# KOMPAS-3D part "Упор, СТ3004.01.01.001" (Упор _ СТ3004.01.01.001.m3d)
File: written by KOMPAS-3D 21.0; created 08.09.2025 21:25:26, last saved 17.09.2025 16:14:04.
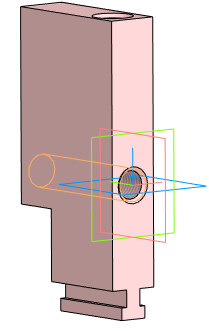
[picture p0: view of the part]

Document properties: Полное имя файла: C:\Users\Lutik\Yandex.Disk\Документы\Новая папка\Стапель №2\Стапель _ СТ3004.00.00.000\Опора _ СТ3004.01.00.000\3D\Кронштейн _ СТ3004.01.01.000\Упор _ СТ3004.01.01.001.m3d

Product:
- Part/product: Упор  | designation СТ3004.01.01.001
    Материал: Сталь 45  ГОСТ 1050-2013 (density 7810 kg/m3)
    Масса: 1.534235
    Форматы листов документа: A3

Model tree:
1. Эскиз:1
2. Элемент выдавливания:1
     Расстояние 1 = 70
3. Эскиз:2  (with: Элемент выдавливания:1)
4. Элемент выдавливания:2
     Расстояние 2 = 25
5. Эскиз:3  (with: Элемент выдавливания:1)
6. Элемент выдавливания:3
     Расстояние 2 = 70
7. Условное изображение резьбы:1  (with: Элемент выдавливания:3)  (labels: M16; cil0_24705-2004 coarse)
     Длина резьбы = 70; Шаг резьбы = 2; Номинальный диаметр резьбы = 16
8. Подгонка:1  (with: Элемент выдавливания:3)
9. Фаска:1  (with: Элемент выдавливания:3)
     Угол = 45; Длина 1 = 2; Длина 2 = 2
10. Эскиз:5  (with: Элемент выдавливания:1)
11. ЛСК:2  (with: Плоскость XY, Плоскость ZX, Плоскость ZY, Ось X, Ось Y, Ось Z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)
     Ось X. Z = 1; Ось Y. X = 1; Ось Z. Y = 1; Координата Y = 15; Координата Z = 80; Точка начала. Y = 15; Точка начала. Z = 80
12. Эскиз:6
13. Присоединительная точка:1
     Перенос X = -10; Расстояние = -10
14. Элемент вращения:1
     Угол 1 = 360
15. Отверстие Ф16x35/2x45°  (labels: Сталь 45  ГОСТ 1050-2013)

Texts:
  KTE.LIST=f.sO0tLtictm5WUlIlwVlc
  Edge1
  Edge2
  СТ3004.01.01.001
